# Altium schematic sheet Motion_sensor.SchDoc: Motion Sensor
size A4; Date: 9/24/2014; Author: P.A.; CompanyName: STMicroelectronics; Address1: 12, Rue Jules HOROWITZ; Address2: 38019 Grenoble; Address3: FRANCE; DocumentNumber: MB1189; Revision: A-01; SheetNumber: 13; SheetTotal: 13; Project: STM32F469I-DISCO
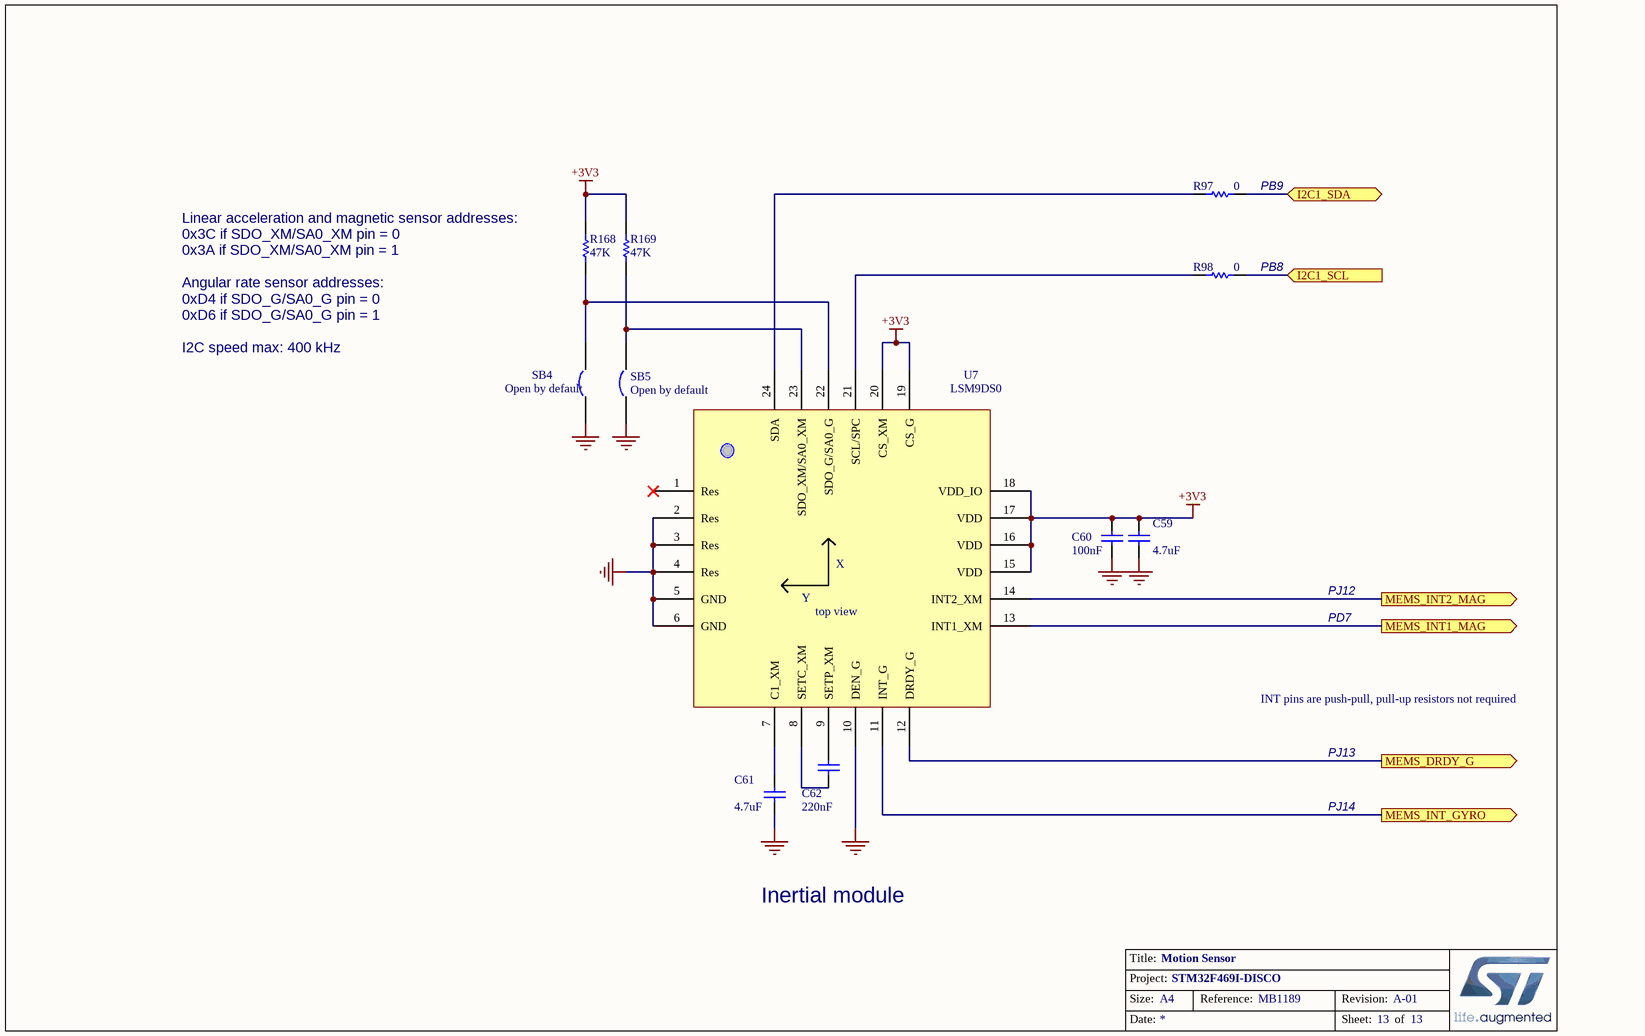
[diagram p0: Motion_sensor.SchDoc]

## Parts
C59  4.7uF  [0603C]
C60  100nF  [0402C]
C61  4.7uF  [0603C]
C62  220nF  [0603C]
R97  0  [0603R]
R98  0  [0603R]
R168  47K  [0603R]
R169  47K  [0603R]
SB4  Open by default  [SB_0603]
SB5  Open by default  [SB_0603]
U7  LSM9DS0  [LGA-24]

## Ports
I2C1_SCL (in), I2C1_SDA (bidir), MEMS_DRDY_G (out), MEMS_INT1_MAG (out), MEMS_INT2_MAG (out), MEMS_INT_GYRO (out)

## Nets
+3V3: C59.1 C60.1 R168.1 R169.1 U7.15(VDD) U7.16(VDD) U7.17(VDD) U7.18(VDD_IO) U7.19(CS_G) U7.20(CS_XM)
GND: C59.2 C60.2 C61.2 SB4.1 SB5.1 U7.2(Res) U7.3(Res) U7.4(Res) U7.5(GND) U7.6(GND) U7.10(DEN_G)
I2C1_SCL: R98.1 ; port I2C1_SCL
I2C1_SDA: R97.1 ; port I2C1_SDA
MEMS_DRDY_G: U7.12(DRDY_G) ; port MEMS_DRDY_G
MEMS_INT1_MAG: U7.13(INT1_XM) ; port MEMS_INT1_MAG
MEMS_INT2_MAG: U7.14(INT2_XM) ; port MEMS_INT2_MAG
MEMS_INT_GYRO: U7.11(INT_G) ; port MEMS_INT_GYRO
NetC61_1: C61.1 U7.7(C1_XM)
NetC62_1: C62.1 U7.9(SETP_XM)
NetC62_2: C62.2 U7.8(SETC_XM)
NetR97_2: R97.2 U7.24(SDA)
NetR98_2: R98.2 U7.21(SCL/SPC)
NetR168_2: R168.2 SB4.2 U7.22(SDO_G/SA0_G)
NetR169_2: R169.2 SB5.2 U7.23(SDO_XM/SA0_XM)

Not connected (* = marked no-connect by the designer): U7 1(Res)*

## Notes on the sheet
- (near R97) PB9
- (near R98) PB8
- Linear acceleration and magnetic sensor addresses:
  0x3C if SDO_XM/SA0_XM pin = 0
  0x3A if SDO_XM/SA0_XM pin = 1
  Angular rate sensor addresses:
  0xD4 if SDO_G/SA0_G pin = 0
  0xD6 if SDO_G/SA0_G pin = 1
  I2C speed max: 400 kHz
- PD7
- PJ12
- INT pins are push-pull, pull-up resistors not required
- PJ13
- PJ14
- Inertial module

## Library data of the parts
C59 C61 = Cap: Capacitor; Value: 10nF; Ordered by: Subcon
C60 C62 = CAP: Capacitor; Value: 100pF; Ordered by: Subcon
R97 R98 = Res1: Resistor; Value: 1K; Ordered by: Subcon
R168 R169 = res1: Resistor; Value: 1K; Ordered by: Subcon
SB4 SB5 = Circuit Breaker: Ordered by: Subcon; Comments: Solder bridge; Fitted: NO
U7 = LSM9DS0: inertial module; Ordered by: STM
